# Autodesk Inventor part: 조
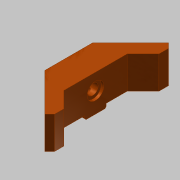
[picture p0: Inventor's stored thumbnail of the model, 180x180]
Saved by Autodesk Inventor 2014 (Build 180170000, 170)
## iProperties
Created: 2019-04
Part Number: 조
Material: 알루미늄 6061
Document SubType Name: Modeling
Designer: mduedu
Density: 1 g/cm^3
Appearance: 매끄러움 - 연한 주황색
Author: mduedu
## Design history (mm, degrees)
sketch "스케치1"
  geometry: L1 (45.962, 0)-(0, -45.962); L2 (0, -45.962)-(-45.962, 0); L3 (-45.962, 0)-(0, 45.962); L4 (0, 45.962)-(45.962, 0); L5 (45.962, 0)-(-45.962, 0); L6 (0, -45.962)-(0, 45.962); 1 further point
  constraints: 12 end point, 2 midpoint, 2 parallel, 2 perpendicular, 1 horizontal
  dimensions: "d0" = 65 distance of L1.end L2.end
extrude "돌출1" new body sketch "스케치1" distance "d2" = 27; taper "d3" = 0 deg
chamfer "모따기1" distance "d4" = 25; stored, may be unused: second distance "d5" = 2, angle "d6" = 45 deg
sketch "스케치2"
  geometry: L1 (-17.678, 28.284)-(-45.962, 0) reference; L2 (-17.678, 28.284)-(17.678, 28.284) reference; L3 (45.962, 0)-(17.678, 28.284) reference; L4 (-45.962, 0)-(0, -45.962) reference; L5 (0, -45.962)-(45.962, 0) reference; L6 (-23.536, 8.284)-(23.536, 8.284); L7 (-23.536, 8.284)-(-38.891, -7.071); L8 (38.891, -7.071)-(23.536, 8.284); 1 further point
  constraints: 6 end point, 3 parallel, 2 point on line
  dimensions: "d7" = 20 distance between parallel lines of L6 L2; "d8" = 10 distance between parallel lines of L1 L7; "d9" = 10 distance between parallel lines of L3 L8
extrude "돌출2" cut sketch "스케치2" stored distance "d10" = 27; taper "d11" = 0 deg
sketch "스케치3"
  geometry: L1 (63.64, -27)-(63.64, 0) reference; L2 (56.569, -27)-(63.64, -27) reference; L3 (-28.284, -27)-(-28.284, 0) reference; L4 (-28.284, -27)-(-21.213, -27) reference; L5 (63.64, -27)-(25.678, -27); L6 (25.678, -27)-(25.678, -24); L7 (25.678, -24)-(63.64, -24); L8 (63.64, -24)-(63.64, -27); L9 (-28.284, -27)-(9.678, -27); L10 (9.678, -27)-(9.678, -24); L11 (9.678, -24)-(-28.284, -24); L12 (-28.284, -24)-(-28.284, -27); L13 (41.213, 0)-(-5.858, 0) reference; L14 (17.678, -27)-(17.678, 0)
  constraints: 18 end point, 4 parallel, 2 horizontal, 2 perpendicular, 1 midpoint, 1 symmetric about line
  dimensions: "d12" = 3 distance between parallel lines of L5 L7; "d14" = 16 distance between parallel lines of L10 L6
extrude "돌출3" cut sketch "스케치3" stored distance "d15" = 27; taper "d16" = 0 deg
sketch "스케치4"
  geometry: L1 (31.536, -27)-(15.536, -27) reference; L2 (31.536, -24)-(47.071, -24) reference; 3 further points
  constraints: 1 midpoint, 1 vertical alignment
  dimensions: "d17" = 12 distance from line of L2 point (23.536, -12)
hole "구멍1" sketch "스케치4" at (23.536, -12) diameter "d18" = 8; stored, may be unused: countersink angle "d22" = 90 deg, drill point angle "d24" = 118 deg; dims "d19" = 6, "d20" = 12.5, "d21" = 2, "d23" = 14
node "작업 평면1"
sketch "스케치5"
  geometry: L1 (0, -15)-(0, 0); L2 (-50, -4)-(50, -4); L3 (50, -4)-(50, -1.75); L4 (-50, -1.75)-(-50, -4); L5 (12, -1.75)-(12, -2.75); L6 (12, -2.75)-(-12, -2.75); L7 (-12, -2.75)-(-12, -1.75); L8 (50, -1.75)-(12, -1.75); L9 (-12, -1.75)-(-50, -1.75); C1 r 4 at (0, 0) reference; 2 further points
  constraints: 18 end point, 4 parallel, 2 midpoint, 2 vertical, 2 vertical alignment, 1 collinear, 1 horizontal, 1 perpendicular, 1 tangent
  dimensions: "d26" = 2.5 diameter of L6 L2; "d28" = 4.5 diameter of L8 L2; "d29" = 24 distance of L5.end L6.end; "d30" = 100 distance between parallel lines of L3 L4
revolve "회전1" sketch "스케치5" stored, may be unused: angle "d31" = 90 deg
chamfer "모따기2" distance "d32" = 5; stored, may be unused: second distance "d33" = 2, angle "d34" = 45 deg
chamfer "모따기3" distance "d35" = 1; stored, may be unused: second distance "d36" = 2, angle "d37" = 45 deg
node "솔리드1"
other parameters: "d25" = -5
